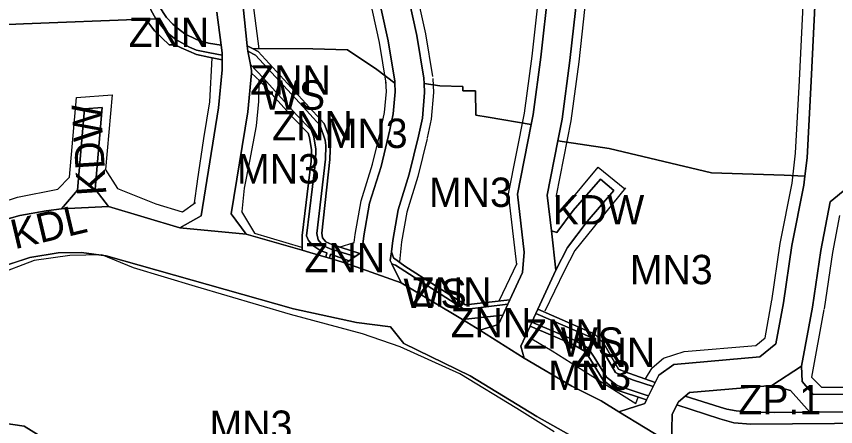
# Model space of a CAD drawing. Extents: x 7417187 to 7419415, y 5539178 to 5540826.
# Drawn here: x 7418455.5 to 7418734.7, y 5539930.4 to 5540070.1 of the extents above; entities that cross this region are included whole.
import ezdxf

# ---------------------------------------------------------------- set-up
doc = ezdxf.new("R2010")
doc.units = 0
for name, color, linetype in [('linie_rozgraniczajace', 7, 'Continuous'), ('linie_zabudowy_nieprzekraczalne', 7, 'Continuous'), ('oznaczenia_przeznaczen', 7, 'Continuous')]:
    doc.layers.add(name, color=color, linetype=linetype)

msp = doc.modelspace()

# ---------------------------------------------------------------- linework, layer by layer
at = {"layer": 'linie_rozgraniczajace'}
for p, q in [((7418465.62, 5540003.87), (7418470.87, 5540004.58)), ((7418470.87, 5540004.58), (7418486.81, 5540005.37)), ((7418486.81, 5540005.37), (7418511.15, 5539998.08)), ((7418448.84, 5540000.15), (7418456.65, 5540002.24)), ((7418456.65, 5540002.24), (7418465.62, 5540003.87)), ((7418511.15, 5539998.08), (7418533.81, 5539995.88)), ((7418533.81, 5539995.88), (7418552.86, 5539990.46)), ((7418460.09, 5539988), (7418448.1, 5539984.08)), ((7418469.7, 5539989.61), (7418460.09, 5539988)), ((7418477.67, 5539989.67), (7418469.7, 5539989.61)), ((7418486.12, 5539988.52), (7418477.67, 5539989.67)), ((7418526.66, 5539977.12), (7418486.12, 5539988.52)), ((7418552.86, 5539990.46), (7418555.5, 5539989.71)), ((7418555.5, 5539989.71), (7418560.96, 5539988.09)), ((7418560.96, 5539988.09), (7418562.19, 5539987.72)), ((7418562.19, 5539987.72), (7418567.71, 5539986.08)), ((7418567.71, 5539986.08), (7418586.55, 5539979.4)), ((7418586.55, 5539979.4), (7418607.51, 5539966.82)), ((7418549.91, 5539970.51), (7418526.66, 5539977.12)), ((7418571.39, 5539965.86), (7418549.91, 5539970.51)), ((7418582.99, 5539964.37), (7418571.39, 5539965.86)), ((7418607.51, 5539966.82), (7418613.43, 5539963.24)), ((7418587.53, 5539958.72), (7418582.99, 5539964.37)), ((7418613.43, 5539963.24), (7418628.48, 5539953.75)), ((7418610.13, 5539947.65), (7418587.53, 5539958.72)), ((7418628.48, 5539953.75), (7418644.75, 5539944.19)), ((7418632.89, 5539933.88), (7418610.13, 5539947.65)), ((7418644.75, 5539944.19), (7418654.76, 5539939.14)), ((7418654.76, 5539939.14), (7418660.83, 5539935.45)), ((7418660.83, 5539935.45), (7418678.67, 5539924.49)), ((7418645.61, 5539926.63), (7418632.89, 5539933.88))]:
    msp.add_line(p, q, dxfattribs=at)
for points in [[(7418584.43, 5540047.42), (7418578.31, 5540051.98), (7418568.28, 5540058.76), (7418556.47, 5540059.02), (7418535.91, 5540059.15), (7418534.13, 5540060.05), (7418529.7, 5540103.31), (7418524.4, 5540131.05), (7418520.81, 5540152.49), (7418517.4, 5540168.52), (7418511.31, 5540190.91), (7418511.09, 5540192.28), (7418515.23, 5540196.73), (7418528.79, 5540195.58), (7418574.35, 5540189.92), (7418582.14, 5540188.28), (7418586.48, 5540182.28), (7418580.42, 5540127.84), (7418578.82, 5540119.95), (7418576.56, 5540096.09), (7418577.38, 5540083.46), (7418582.16, 5540061.73), (7418584.4, 5540048.01)], [(7418525.56, 5540056.85), (7418525.58, 5540055.31), (7418521.06, 5540056.24), (7418516.9, 5540057.14), (7418511.67, 5540059.39), (7418509.62, 5540060.43), (7418507.49, 5540060.45), (7418502.49, 5540065.17), (7418500.6, 5540067.77), (7418499.1, 5540068.94), (7418498.87, 5540069.14), (7418503.02, 5540069.31), (7418506.53, 5540064.88), (7418509.82, 5540062.23), (7418511.85, 5540061.1), (7418514.43, 5540059.6), (7418516.85, 5540058.64), (7418521.36, 5540057.71)], [(7418535.91, 5540059.15), (7418537.91, 5540058.13), (7418560.4, 5540033.66), (7418562.47, 5540027.8), (7418562.34, 5540021.35), (7418559.54, 5539996.22), (7418559.78, 5539994.68), (7418560.89, 5539993.29), (7418562.92, 5539992.38), (7418572.54, 5539989.37), (7418570.96, 5539988.3), (7418562.39, 5539990.97), (7418559.94, 5539992.07), (7418558.36, 5539994.05), (7418557.91, 5539996.16), (7418560.84, 5540021.44), (7418560.95, 5540026.09), (7418560.75, 5540027.93), (7418559.04, 5540032.99), (7418552.01, 5540040.66), (7418536.99, 5540056.91), (7418534.32, 5540058.28), (7418534.13, 5540060.05)], [(7418570.96, 5539988.3), (7418568.89, 5539986.88), (7418562.49, 5539989.14), (7418562.19, 5539987.72), (7418560.96, 5539988.09), (7418561.27, 5539989.59), (7418559.17, 5539990.24), (7418556.51, 5539992.12), (7418555.03, 5539993.73), (7418554.33, 5539995.34), (7418557.38, 5540020.6), (7418557.52, 5540024.87), (7418556.89, 5540029.04), (7418555.98, 5540031.44), (7418550.8, 5540036.73), (7418539.64, 5540049.09), (7418535.21, 5540053.67), (7418534.32, 5540058.28), (7418536.99, 5540056.91), (7418552.01, 5540040.66), (7418559.04, 5540032.99), (7418560.75, 5540027.93), (7418560.95, 5540026.09), (7418560.84, 5540021.44), (7418557.91, 5539996.16), (7418558.36, 5539994.05), (7418559.94, 5539992.07), (7418562.39, 5539990.97)], [(7418584.43, 5540047.42), (7418584.55, 5540044.44), (7418583.92, 5540036.92), (7418582.78, 5540031.47), (7418579.74, 5540019), (7418575.85, 5540006.53), (7418573.9, 5539995.32), (7418573.19, 5539989.82), (7418572.54, 5539989.37), (7418562.92, 5539992.38), (7418560.89, 5539993.29), (7418559.78, 5539994.68), (7418559.54, 5539996.22), (7418562.34, 5540021.35), (7418562.47, 5540027.8), (7418560.4, 5540033.66), (7418537.91, 5540058.13), (7418535.91, 5540059.15), (7418556.47, 5540059.02), (7418568.28, 5540058.76), (7418578.31, 5540051.98)], [(7418560.96, 5539988.09), (7418555.5, 5539989.71), (7418552.86, 5539990.46), (7418552.84, 5539995.52), (7418555.89, 5540020.78), (7418556.04, 5540024.65), (7418555.41, 5540028.82), (7418554.91, 5540030.39), (7418549.69, 5540035.72), (7418538.53, 5540048.08), (7418535.55, 5540050.73), (7418535.62, 5540051.52), (7418535.21, 5540053.67), (7418539.64, 5540049.09), (7418550.8, 5540036.73), (7418555.98, 5540031.44), (7418556.89, 5540029.04), (7418557.52, 5540024.87), (7418557.38, 5540020.6), (7418554.33, 5539995.34), (7418555.03, 5539993.73), (7418556.51, 5539992.12), (7418559.17, 5539990.24), (7418561.27, 5539989.59)], [(7418552.86, 5539990.46), (7418533.81, 5539995.88), (7418528.69, 5540002.89), (7418534.32, 5540037.64), (7418535.55, 5540050.73), (7418538.53, 5540048.08), (7418549.69, 5540035.72), (7418554.91, 5540030.39), (7418555.41, 5540028.82), (7418556.04, 5540024.65), (7418555.89, 5540020.78), (7418552.84, 5539995.52)], [(7418630.92, 5540033.25), (7418626.27, 5540009.59), (7418628.57, 5539989.79), (7418627.93, 5539982.83), (7418623.64, 5539973.53), (7418608.54, 5539971.82), (7418587.84, 5539985.08), (7418583.98, 5539987.92), (7418583.29, 5539989.91), (7418583.79, 5539993.83), (7418585.59, 5540004.18), (7418589.38, 5540016.32), (7418592.54, 5540029.27), (7418593.83, 5540035.49), (7418594.56, 5540044.22), (7418594.44, 5540047.23), (7418599.79, 5540046.47), (7418607.66, 5540046.24), (7418607.64, 5540044.81), (7418611.92, 5540044.73), (7418611.99, 5540036.51), (7418616.22, 5540035.78)], [(7418486.81, 5540005.37), (7418470.87, 5540004.58), (7418476.25, 5540010.89), (7418478.67, 5540038.66), (7418484.74, 5540039.11), (7418482.32, 5540011.29)], [(7418724.16, 5540015.73), (7418723.77, 5540012.65), (7418719.74, 5539992.11), (7418716.85, 5539972.56), (7418714.3, 5539958.62), (7418708.82, 5539954.11), (7418679.57, 5539951.59), (7418674.42, 5539947.87), (7418673.19, 5539945.39), (7418662.54, 5539949.1), (7418660.72, 5539949.93), (7418655.62, 5539958.67), (7418652.61, 5539961.88), (7418633.18, 5539970.34), (7418639.34, 5539983.7), (7418643.27, 5539991.34), (7418649.94, 5540000.22), (7418659.04, 5540010.76), (7418654.5, 5540014.68), (7418645.26, 5540003.98), (7418639.64, 5539996.5), (7418637.79, 5539997.06), (7418636.38, 5540009.19), (7418640.03, 5540027.78), (7418657.44, 5540025.07), (7418692.32, 5540016.78), (7418717.08, 5540016.01)], [(7418639.34, 5539983.7), (7418637.79, 5539997.06), (7418639.64, 5539996.5), (7418645.26, 5540003.98), (7418654.5, 5540014.68), (7418659.04, 5540010.76), (7418649.94, 5540000.22), (7418643.27, 5539991.34)], [(7418568.89, 5539986.88), (7418567.71, 5539986.08), (7418562.19, 5539987.72), (7418562.49, 5539989.14)], [(7418623.64, 5539973.53), (7418622.96, 5539972.05), (7418608.18, 5539970.26), (7418584.71, 5539985.43), (7418583.44, 5539985.82), (7418582.9, 5539986.93), (7418583.29, 5539989.91), (7418583.98, 5539987.92), (7418587.84, 5539985.08), (7418608.54, 5539971.82)], [(7418622.96, 5539972.05), (7418621.27, 5539968.38), (7418607.51, 5539966.82), (7418586.55, 5539979.4), (7418583.44, 5539985.82), (7418584.71, 5539985.43), (7418608.18, 5539970.26)], [(7418613.43, 5539963.24), (7418607.51, 5539966.82), (7418621.27, 5539968.38), (7418619.8, 5539965.19)], [(7418672.53, 5539944.06), (7418670.94, 5539940.85), (7418669.76, 5539941.19), (7418664.3, 5539943.05), (7418660.16, 5539944.42), (7418656.56, 5539947.17), (7418652.39, 5539954.07), (7418650.34, 5539957.11), (7418645.88, 5539959.71), (7418631.17, 5539965.97), (7418632.52, 5539968.9), (7418651.72, 5539960.63), (7418654.41, 5539957.77), (7418659.67, 5539948.77), (7418662.8, 5539947.33), (7418665.74, 5539946.23)], [(7418673.19, 5539945.39), (7418672.53, 5539944.06), (7418665.74, 5539946.23), (7418662.8, 5539947.33), (7418659.67, 5539948.77), (7418654.41, 5539957.77), (7418651.72, 5539960.63), (7418632.52, 5539968.9), (7418633.18, 5539970.34), (7418652.61, 5539961.88), (7418655.62, 5539958.67), (7418660.72, 5539949.93), (7418662.54, 5539949.1)], [(7418670.94, 5539940.85), (7418670.25, 5539939.45), (7418659.52, 5539943.05), (7418655.43, 5539946.15), (7418651.12, 5539953.26), (7418649.29, 5539955.98), (7418645.21, 5539958.36), (7418630.54, 5539964.6), (7418631.17, 5539965.97), (7418645.88, 5539959.71), (7418650.34, 5539957.11), (7418652.39, 5539954.07), (7418656.56, 5539947.17), (7418660.16, 5539944.42), (7418664.3, 5539943.05), (7418669.76, 5539941.19)], [(7418670.25, 5539939.45), (7418669.67, 5539938.29), (7418660.83, 5539935.45), (7418654.76, 5539939.14), (7418644.75, 5539944.19), (7418628.48, 5539953.75), (7418627.39, 5539957.76), (7418630.54, 5539964.6), (7418645.21, 5539958.36), (7418649.29, 5539955.98), (7418651.12, 5539953.26), (7418655.43, 5539946.15), (7418659.52, 5539943.05)], [(7418725.92, 5539935.3), (7418713.87, 5539935.2), (7418704.07, 5539935.42), (7418700.81, 5539935.7), (7418697.61, 5539936.37), (7418695.36, 5539937.06), (7418683.37, 5539940.73), (7418684.89, 5539942.01), (7418712.88, 5539944.42), (7418719.32, 5539942.7)]]:
    msp.add_lwpolyline(points, close=True, dxfattribs=at)
for points in [[(7418455.21, 5540159.2), (7418458.58, 5540156.01), (7418463.38, 5540150.96), (7418469.78, 5540142.69), (7418473.44, 5540135.76), (7418476.13, 5540129.63), (7418480.76, 5540118.92), (7418487.68, 5540103.18), (7418498.7, 5540078.12), (7418501.27, 5540072.34), (7418503.02, 5540069.31), (7418498.87, 5540069.14), (7418457.92, 5540067.55), (7418377.24, 5540064.07)], [(7418731.05, 5540145.52), (7418726.34, 5540048.02), (7418724.95, 5540021.93), (7418724.16, 5540015.73), (7418717.08, 5540016.01), (7418692.32, 5540016.78), (7418657.44, 5540025.07), (7418640.03, 5540027.78), (7418641.46, 5540035.05), (7418644.11, 5540055.05), (7418646.71, 5540078.27)], [(7418738.47, 5540011.64), (7418732.84, 5540006.91), (7418729.6, 5539990.41), (7418726.75, 5539971.09), (7418723.06, 5539951), (7418712.88, 5539944.42), (7418684.89, 5539942.01), (7418683.37, 5539940.73), (7418681.07, 5539938.77), (7418680.58, 5539937.78), (7418678.94, 5539934.48), (7418678.67, 5539924.49), (7418660.83, 5539935.45), (7418669.67, 5539938.29), (7418670.25, 5539939.45), (7418670.94, 5539940.85), (7418672.53, 5539944.06), (7418673.19, 5539945.39), (7418674.42, 5539947.87), (7418679.57, 5539951.59), (7418708.82, 5539954.11), (7418714.3, 5539958.62), (7418716.85, 5539972.56), (7418719.74, 5539992.11), (7418723.77, 5540012.65), (7418724.16, 5540015.73), (7418724.95, 5540021.93), (7418726.34, 5540048.02), (7418731.05, 5540145.52)], [(7418529.7, 5540103.31), (7418534.13, 5540060.05), (7418534.32, 5540058.28), (7418535.21, 5540053.67), (7418535.62, 5540051.52), (7418535.55, 5540050.73), (7418534.32, 5540037.64), (7418528.69, 5540002.89), (7418533.81, 5539995.88), (7418511.15, 5539998.08), (7418518.45, 5540002.23), (7418524.4, 5540038.91), (7418525.62, 5540051.93), (7418525.58, 5540055.31), (7418525.56, 5540056.85), (7418525.55, 5540057.7), (7418525.21, 5540060.34), (7418523.75, 5540071.5)], [(7418587.31, 5540084.87), (7418591.98, 5540063.61), (7418594.37, 5540049.03), (7418594.44, 5540047.23), (7418594.56, 5540044.22), (7418593.83, 5540035.49), (7418592.54, 5540029.27), (7418589.38, 5540016.32), (7418585.59, 5540004.18), (7418583.79, 5539993.83), (7418583.29, 5539989.91), (7418582.9, 5539986.93), (7418583.44, 5539985.82), (7418586.55, 5539979.4), (7418567.71, 5539986.08), (7418568.89, 5539986.88), (7418570.96, 5539988.3), (7418572.54, 5539989.37), (7418573.19, 5539989.82), (7418573.9, 5539995.32), (7418575.85, 5540006.53), (7418579.74, 5540019), (7418582.78, 5540031.47), (7418583.92, 5540036.92), (7418584.55, 5540044.44), (7418584.43, 5540047.42), (7418584.4, 5540048.01), (7418582.16, 5540061.73), (7418577.38, 5540083.46)], [(7418636.82, 5540079.76), (7418634.18, 5540056.26), (7418631.59, 5540036.67), (7418630.92, 5540033.25), (7418616.22, 5540035.78), (7418611.99, 5540036.51), (7418611.92, 5540044.73), (7418607.64, 5540044.81), (7418607.66, 5540046.24), (7418599.79, 5540046.47), (7418594.44, 5540047.23), (7418594.37, 5540049.03), (7418591.98, 5540063.61), (7418587.31, 5540084.87)], [(7418646.71, 5540078.27), (7418644.11, 5540055.05), (7418641.46, 5540035.05), (7418640.03, 5540027.78), (7418636.38, 5540009.19), (7418637.79, 5539997.06), (7418639.34, 5539983.7), (7418633.18, 5539970.34), (7418632.52, 5539968.9), (7418631.17, 5539965.97), (7418630.54, 5539964.6), (7418627.39, 5539957.76), (7418628.48, 5539953.75), (7418613.43, 5539963.24), (7418619.8, 5539965.19), (7418621.27, 5539968.38), (7418622.96, 5539972.05), (7418623.64, 5539973.53), (7418627.93, 5539982.83), (7418628.57, 5539989.79), (7418626.27, 5540009.59), (7418630.92, 5540033.25), (7418631.59, 5540036.67), (7418634.18, 5540056.26), (7418636.82, 5540079.76)], [(7418504.04, 5540073.69), (7418506.68, 5540069.75), (7418508.76, 5540067.51), (7418510.36, 5540066.09), (7418512.89, 5540064.2), (7418516.82, 5540062.21), (7418520.97, 5540060.97), (7418525.21, 5540060.34), (7418525.55, 5540057.7), (7418525.56, 5540056.85), (7418521.36, 5540057.71), (7418516.85, 5540058.64), (7418514.43, 5540059.6), (7418511.85, 5540061.1), (7418509.82, 5540062.23), (7418506.53, 5540064.88), (7418503.02, 5540069.31), (7418501.27, 5540072.34)], [(7418523.75, 5540071.5), (7418525.21, 5540060.34), (7418520.97, 5540060.97), (7418516.82, 5540062.21), (7418512.89, 5540064.2), (7418510.36, 5540066.09), (7418508.76, 5540067.51), (7418506.68, 5540069.75), (7418504.04, 5540073.69)], [(7418377.24, 5540064.07), (7418457.92, 5540067.55), (7418498.87, 5540069.14), (7418499.1, 5540068.94), (7418500.6, 5540067.77), (7418502.49, 5540065.17), (7418507.49, 5540060.45), (7418509.62, 5540060.43), (7418511.67, 5540059.39), (7418516.9, 5540057.14), (7418521.06, 5540056.24), (7418525.58, 5540055.31), (7418525.62, 5540051.93), (7418524.4, 5540038.91), (7418518.45, 5540002.23), (7418511.15, 5539998.08), (7418486.81, 5540005.37), (7418482.32, 5540011.29), (7418484.74, 5540039.11), (7418478.67, 5540038.66), (7418476.25, 5540010.89), (7418470.87, 5540004.58), (7418465.62, 5540003.87), (7418456.65, 5540002.24), (7418448.84, 5540000.15)], [(7418744.32, 5539941.44), (7418727, 5539941.31), (7418723.25, 5539945.78), (7418723.06, 5539951), (7418726.75, 5539971.09), (7418729.6, 5539990.41), (7418732.84, 5540006.91), (7418738.47, 5540011.64)], [(7418467.69, 5539924.67), (7418458.16, 5539930.52), (7418451.22, 5539931.57), (7418435.2, 5539937.16), (7418415.61, 5539942.33), (7418401.3, 5539948.39), (7418395.47, 5539951.6), (7418395.62, 5539957.92), (7418405.44, 5539962.93), (7418431.16, 5539976.28), (7418448.1, 5539984.08), (7418460.09, 5539988), (7418469.7, 5539989.61), (7418477.67, 5539989.67), (7418486.12, 5539988.52), (7418526.66, 5539977.12), (7418549.91, 5539970.51), (7418571.39, 5539965.86), (7418582.99, 5539964.37), (7418587.53, 5539958.72), (7418610.13, 5539947.65), (7418632.89, 5539933.88), (7418645.61, 5539926.63)], [(7418420.25, 5539929.52), (7418416.54, 5539930.38), (7418416.54, 5539930.27), (7418414.01, 5539930.78), (7418406.38, 5539932.75), (7418400.14, 5539935.02), (7418396.28, 5539937.71), (7418393.8, 5539941.09), (7418386.7, 5539950.77), (7418385.93, 5539952.31), (7418393.1, 5539956.63), (7418395.62, 5539957.92), (7418395.47, 5539951.6), (7418401.3, 5539948.39), (7418415.61, 5539942.33), (7418435.2, 5539937.16), (7418451.22, 5539931.57), (7418458.16, 5539930.52), (7418467.69, 5539924.67)], [(7418744.58, 5539935.44), (7418725.92, 5539935.3), (7418719.32, 5539942.7), (7418712.88, 5539944.42), (7418723.06, 5539951), (7418723.25, 5539945.78), (7418727, 5539941.31), (7418744.32, 5539941.44)], [(7418748.43, 5539931.6), (7418705.75, 5539931.19), (7418699.93, 5539931.66), (7418695.21, 5539933.05), (7418680.58, 5539937.78), (7418681.07, 5539938.77), (7418683.37, 5539940.73), (7418695.36, 5539937.06), (7418697.61, 5539936.37), (7418700.81, 5539935.7), (7418704.07, 5539935.42), (7418713.87, 5539935.2), (7418725.92, 5539935.3), (7418744.58, 5539935.44)], [(7418744.21, 5539807.3), (7418734.61, 5539812.19), (7418715.09, 5539820.74), (7418699.69, 5539829.75), (7418690.19, 5539837.84), (7418689.12, 5539839.11), (7418686.76, 5539843.67), (7418685.68, 5539850.17), (7418685.47, 5539862.78), (7418685.36, 5539897.14), (7418683.53, 5539911.12), (7418678.67, 5539924.49), (7418678.94, 5539934.48), (7418680.58, 5539937.78), (7418695.21, 5539933.05), (7418699.93, 5539931.66), (7418705.75, 5539931.19), (7418748.43, 5539931.6)]]:
    msp.add_lwpolyline(points, dxfattribs=at)
at = {"layer": 'linie_zabudowy_nieprzekraczalne'}
for points in [[(7418515.99, 5540187.06), (7418520.8, 5540169.35), (7418524.25, 5540153.15), (7418527.86, 5540131.58), (7418532.58, 5540101.82), (7418538.14, 5540059.1)], [(7418712.91, 5539973.19), (7418715.8, 5539992.79), (7418719.82, 5540013.27), (7418721.03, 5540023.54), (7418722.35, 5540048.22), (7418726.86, 5540141.66)], [(7418581.47, 5540047.35), (7418579.21, 5540061.17), (7418574.4, 5540083.04), (7418573.56, 5540096.13), (7418575.82, 5540119.97)], [(7418591.74, 5540118.46), (7418589.61, 5540095.89), (7418590.29, 5540085.29), (7418594.93, 5540064.18), (7418597.3, 5540049.69)], [(7418626.04, 5539985.54), (7418623.23, 5540009.71), (7418628.63, 5540037.16), (7418631.21, 5540056.62), (7418633.85, 5540080.2), (7418636.72, 5540095.41), (7418639.43, 5540108.91)], [(7418655.11, 5540105.69), (7418652.46, 5540092.53), (7418649.68, 5540077.83), (7418647.09, 5540054.68), (7418644.43, 5540034.56), (7418639.42, 5540009.08), (7418640.07, 5540003.48)], [(7418517.22, 5540014), (7418519.36, 5540028.51), (7418521.41, 5540040.99), (7418522.16, 5540056.01)], [(7418538.11, 5540048.53), (7418537.95, 5540041.13), (7418537.15, 5540032.89), (7418534.87, 5540020.78), (7418533.07, 5540011.65), (7418532.27, 5540003.64)], [(7418579.84, 5540032.03), (7418580.94, 5540037.36), (7418581.55, 5540044.51), (7418581.4, 5540048.08)], [(7418597.38, 5540048.97), (7418597.57, 5540044.16), (7418596.81, 5540035.06), (7418595.49, 5540028.71)], [(7418473.59, 5540015.3), (7418476, 5540042.48)], [(7418476, 5540042.48), (7418488.11, 5540043.36)], [(7418488.11, 5540043.36), (7418485.8, 5540017.94)], [(7418570.55, 5539993.08), (7418570.95, 5539995.83), (7418572.93, 5540007.24), (7418576.85, 5540019.8), (7418579.89, 5540032.23)], [(7418595.45, 5540028.51), (7418592.28, 5540015.52), (7418588.52, 5540003.47), (7418586.76, 5539993.36), (7418586.02, 5539986.56)], [(7418642.65, 5540005.39), (7418653.76, 5540018.8)], [(7418653.76, 5540018.8), (7418662.87, 5540011.43)], [(7418485.75, 5540018.02), (7418489.96, 5540011.47), (7418503.01, 5540006.22), (7418511.95, 5540003.5)], [(7418469.64, 5540011.31), (7418473.59, 5540015.3)], [(7418516.2, 5540006.63), (7418517.21, 5540013.9)], [(7418412.18, 5539991.66), (7418440.04, 5540003.4), (7418455.81, 5540008.56), (7418469.64, 5540011.31)], [(7418663.08, 5540011.67), (7418645.74, 5539990.36)], [(7418512.06, 5540003.49), (7418516.47, 5540006.69)], [(7418640.07, 5540003.48), (7418642.65, 5540005.39)], [(7418532.22, 5540003.62), (7418536.65, 5539996.28)], [(7418736.01, 5540002.32), (7418733.55, 5539989.74), (7418730.7, 5539970.46)], [(7418536.65, 5539996.28), (7418552.59, 5539991.46)], [(7418565.5, 5539991.49), (7418570.55, 5539993.08)], [(7418638.78, 5539928.55), (7418626.03, 5539936.56), (7418606.61, 5539948.32), (7418586.21, 5539957.51), (7418573.41, 5539962.03), (7418548.93, 5539968.54), (7418516.48, 5539978.08), (7418495.35, 5539984.51), (7418484.59, 5539988.84), (7418473.66, 5539988.69), (7418461.51, 5539986.93), (7418448.39, 5539981.96), (7418421.59, 5539970.74), (7418411.52, 5539965.96)], [(7418645.74, 5539990.36), (7418642.13, 5539983.35)], [(7418619.98, 5539973.25), (7418626.13, 5539986.07)], [(7418642.13, 5539983.35), (7418635.51, 5539969.71)], [(7418710.59, 5539960.6), (7418712.94, 5539973.4)], [(7418730.66, 5539970.25), (7418726.44, 5539947.2)], [(7418632.71, 5539963.68), (7418631.15, 5539960.33)], [(7418631.15, 5539960.33), (7418638.1, 5539956.14), (7418651.02, 5539948.02), (7418666.59, 5539938.23)], [(7418707.51, 5539958.01), (7418710.59, 5539960.6)], [(7418683.07, 5539955.91), (7418707.51, 5539958.01)], [(7418669.81, 5539946.69), (7418672.13, 5539950.39), (7418675.98, 5539953.68), (7418683.07, 5539955.91)], [(7418726.44, 5539947.2), (7418729.89, 5539943.79)], [(7418729.89, 5539943.79), (7418737.7, 5539943.79)], [(7418666.59, 5539938.23), (7418667.42, 5539940.41)]]:
    msp.add_lwpolyline(points, dxfattribs=at)

# ---------------------------------------------------------------- texts
at = {"layer": 'oznaczenia_przeznaczen'}
for s, p in [('ZNN', (7418493.72, 5540059.7)), ('ZNN', (7418535.17, 5540043.49)), ('WS', (7418539.14, 5540038.3)), ('ZNN', (7418542.62, 5540027.85)), ('MN3', (7418560.57, 5540025.29)), ('MN3', (7418530.66, 5540013.19)), ('MN3', (7418596.08, 5540005.21)), ('KDW', (7418638.25, 5539999.24)), ('ZNN', (7418553.65, 5539982.95)), ('MN3', (7418664.51, 5539978.89)), ('WS', (7418587.4, 5539970.76)), ('ZNN', (7418589.92, 5539971.28)), ('ZNN', (7418603.45, 5539960.81)), ('ZNN', (7418628.15, 5539956.89)), ('WS', (7418640.94, 5539954.16)), ('ZNN', (7418645.71, 5539950.68)), ('MN3', (7418636.72, 5539942.88)), ('ZP.1', (7418701.5, 5539934.61)), ('MN3', (7418521.29, 5539925.86))]:
    msp.add_text(s, height=10, dxfattribs=at).set_placement(p)
for s, rotation, p in [('KDW', 93.5199, (7418486.17, 5540009.32)), ('KDL', 13.3009, (7418454.9, 5539990.77))]:
    msp.add_text(s, height=10, rotation=rotation, dxfattribs=at).set_placement(p)

doc.saveas('drawing.dxf')
